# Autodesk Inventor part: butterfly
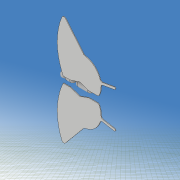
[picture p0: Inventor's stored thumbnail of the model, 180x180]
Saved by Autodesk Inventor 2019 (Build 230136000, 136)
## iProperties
Created: 2021-05
Part Number: butterfly
Material: 一般
Document SubType Name: Modeling
Designer: kikut
Density: 1 g/cm^3
Appearance: 既定
Author: kikut
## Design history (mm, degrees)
sketch "スケッチ1"
  geometry: L1 (80, 60)-(-80, 60); L2 (-80, 60)-(-80, -60); L3 (-80, -60)-(80, -60); L4 (80, -60)-(80, 60); L5 (80, 60)-(-80, -60); L6 (-80, 60)-(80, -60); 1 further point
  constraints: 12 end point, 2 midpoint, 2 parallel, 1 horizontal, 1 perpendicular
  dimensions: "d0" = 160 distance of L2.end L3.end; "d1" = 120 distance of L1.end L2.end
extrude "押し出し1" new body sketch "スケッチ1" stored distance "d2" = 0.6; taper "d3" = 0 deg
sketch "スケッチ2"
  geometry: L1 (-140, 0)-(140, 0) reference; L2 (0, -54)-(20, -30); L3 (0, 54)-(20, 30); L4 (0, -3)-(6.514, -3); L5 (6.514, -3)-(16, -6); L6 (16, -6)-(24, -3); L7 (24, -3)-(33.716, -3); L8 (0, 3)-(6.514, 3); L9 (6.514, 3)-(16, 6); L10 (16, 6)-(24, 3); L11 (24, 3)-(33.716, 3); L12 (0, -98)-(0, 98) reference; L13 (-100, -70)-(100, -70); L14 (100, -70)-(100, 70); L15 (100, 70)-(-100, 70); L16 (-100, 70)-(-100, -70); L17 (-100, -70)-(100, 70); L18 (100, -70)-(-100, 70); A1 r 60 centre (54.312, 28.5) between (0, 54) and (0, 3); A2 r 60 centre (54.312, -28.5) between (0, -3) and (0, -54); A3 r 18.111 centre (18, -12) between (20, -30) and (33.716, -3); A4 r 18.111 centre (18, 12) between (33.716, 3) and (20, 30); 1 further point
  constraints: 32 end point, 8 point on circle, 8 symmetric about line, 4 centre point, 3 horizontal, 2 collinear, 2 midpoint, 2 parallel, 1 perpendicular
  dimensions: "d5" = 60 radius of A1; "d6" = 6 distance of L8.start L4.start; "d7" = 108 distance of L3.start L2.start; "d8" = 0 horizontal distance of L3.start L8.start; "d9" = 60 distance of L3.end L2.end; "d10" = 0 horizontal distance of point (0, 0) L3.start; "d11" = 20 horizontal distance of L3.start L3.end; "d12" = 24 distance of A4.centre A3.centre; "d13" = 6 distance of L11.end L7.end; "d14" = 12 distance of L9.end L5.end; "d15" = 16 distance from line of L12 L5.end; "d16" = 24 distance from line of L6.end L12; "d17" = 200 distance of L14.end L15.end; "d18" = 140 distance of L15.end L13.start; "d30" = 18 distance from line of L12 A4.centre
extrude "押し出し2" cut sketch "スケッチ2" stored distance "d19" = 10; taper "d20" = 0 deg
sketch "スケッチ3"
  geometry: L1 (49.705, -18.374)-(33.948, -15.596); L2 (33.948, -15.596)-(34.295, -13.626); L3 (34.295, -13.626)-(50.052, -16.404); L4 (50.052, -16.404)-(49.705, -18.374); L5 (49.705, -18.374)-(34.295, -13.626); L6 (33.948, -15.596)-(50.052, -16.404); L7 (50.052, 16.404)-(34.295, 13.626); L8 (34.295, 13.626)-(33.948, 15.596); L9 (33.948, 15.596)-(49.705, 18.374); L10 (49.705, 18.374)-(50.052, 16.404); L11 (50.052, 16.404)-(33.948, 15.596); L12 (34.295, 13.626)-(49.705, 18.374); L13 (-112, 0)-(112, 0) reference; L14 (0, -84)-(0, 84) reference; 3 further points
  constraints: 24 end point, 4 midpoint, 4 parallel, 2 perpendicular, 2 symmetric about line
  dimensions: "d21" = 2 distance of L3.end L1.start; "d22" = 2 distance of L9.end L7.start; "d23" = 16 distance of L8.end L9.end; "d24" = 42 distance from line of L14 point (42, 16); "d25" = 32 distance of point (42, 16) point (42, -16); "d26" = 10 deg angle of L7 L13
extrude "押し出し3" join sketch "スケッチ3" distance "d27" = 0.6; taper "d28" = 0 deg
fillet "フィレット1" dims "d31" = 2
fillet "フィレット2" dims "d32" = 1
sketch "スケッチ4"
  geometry: L1 (7, -5)-(1, -5); L2 (19.604, 0)-(-61.477, 0) reference; L3 (0, -10.86)-(0, 2.16) reference; L4 (-19.5, 0.3)-(-2.073, 0.3) reference; L5 (3, -5)-(-7, -5); L6 (0, -8)-(-4, -8); L7 (-5.09, 6.534)-(-4.607, 25.024); A1 r 3 centre (4, -5) between (1, -5) and (7, -5); A2 r 3 centre (0, -5) between (0, -8) and (3, -5); A3 r 3 centre (-4, -5) between (-7, -5) and (-4, -8); 1 further point
  constraints: 8 end point, 6 point on circle, 3 centre point, 2 horizontal, 2 point on line
  dimensions: "d33" = 5 distance between parallel lines of L1 L2; "d34" = 0 vertical distance of L1.start A1.centre; "d35" = 3 radius of A1; "d36" = 1 distance from line of L3 L1.end; "d45" = 0 vertical distance of L6.end L6.start; "d46" = 3 radius of A2; "d47" = 0 distance between parallel lines of L5 L1; "d48" = 4 distance of A1.centre A2.centre; "d49" = 0 horizontal distance of A3.centre L6.end; "d50" = 4 distance of L6.start L6.end
revolve "回転1" sketch "スケッチ4" stored, may be unused: angle "d51" = 90 deg
sketch "スケッチ5"
  geometry: L1 (-8, -5)-(-24, -5); L2 (-11, -8)-(-21, -8); L3 (21.979, 0)-(-61.872, 0) reference; L4 (0, -13.303)-(0, 2.567) reference; A1 r 3 centre (-11, -5) between (-11, -8) and (-8, -5); A2 r 3 centre (-21, -5) between (-24, -5) and (-21, -8); 1 further point
  constraints: 4 end point, 4 point on circle, 2 centre point, 1 horizontal
  dimensions: "d52" = 5 distance between parallel lines of L3 L1; "d53" = 3 radius of A1; "d54" = 3 radius of A2; "d55" = 0 distance from line of L1 A1.centre; "d56" = 0 distance from line of L1 A2.centre; "d57" = 10 distance of L2.start L2.end; "d58" = 90 deg dimension on A1.centre L2.start L1.start; "d59" = 90 deg dimension on A2.centre L1.end L2.end; "d60" = 8 distance from line of L1.start L4
revolve "回転2" sketch "スケッチ5" stored, may be unused: angle "d61" = 90 deg
node "ソリッド1"
